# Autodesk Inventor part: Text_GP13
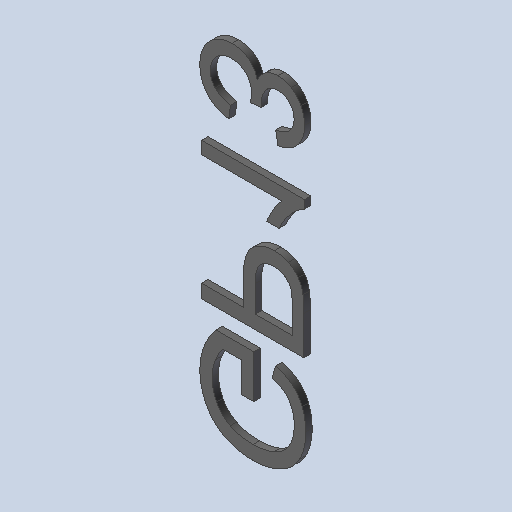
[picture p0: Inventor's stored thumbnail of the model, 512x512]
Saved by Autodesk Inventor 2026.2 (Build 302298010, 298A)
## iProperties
Created: 2026-10
Part Number: Text_GP13
Material: Générique
Document SubType Name: Modeling
Designer: mel
Density: 1 g/cm^3
Appearance: Par défaut
Author: mel
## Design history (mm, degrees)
feature "Base1"
feature "Base2"
feature "Base3"
feature "Base4"
node "Solide1"
node "Solide2"
node "Solide3"
node "Solide4"
